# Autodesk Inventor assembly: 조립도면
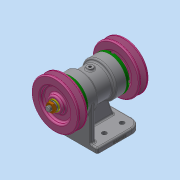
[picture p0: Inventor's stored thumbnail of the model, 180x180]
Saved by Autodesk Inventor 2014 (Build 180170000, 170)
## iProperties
Created: 2020-06
Part Number: 조립도면
Document SubType Name: Weldment
Designer: kh
Weld Material: Welded Aluminum-6061
Author: kh
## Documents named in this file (12)
- C:\Users\kh\Desktop\인벤터시험\조립도면.iam
- C:\Users\kh\Desktop\인벤터시험\본체.ipt
- C:\Users\kh\Desktop\인벤터시험\V-벨트풀리.ipt
- C:\Users\kh\Desktop\인벤터시험\너트 M10.ipt
- C:\Users\kh\Desktop\인벤터시험\베어링 6204.ipt
- C:\Users\kh\Desktop\인벤터시험\볼트 M4.ipt
- C:\Users\kh\Desktop\인벤터시험\스프링 와셔 10.ipt
- C:\Users\kh\Desktop\인벤터시험\오일 실 20 32 5.ipt
- C:\Users\kh\Desktop\인벤터시험\축.ipt
- C:\Users\kh\Desktop\인벤터시험\커버.ipt
- C:\Users\kh\Desktop\인벤터시험\키 5x5x12.ipt
- C:\Users\kh\Desktop\인벤터시험\평면 와셔 10x21.ipt
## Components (2 placed, 1 different names)
1. V-벨트풀리:1 — Angle:2, Mate:24, Mate:26
2. V-벨트풀리:2 — Mate:23, Angle:1, Mate:27, Mate:37
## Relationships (7: Mate 5, Angle 2)
- Mate:23: V-벨트풀리:2
- Angle:1: V-벨트풀리:2
- Angle:2: V-벨트풀리:1
- Mate:24: V-벨트풀리:1
- Mate:26: V-벨트풀리:1
- Mate:27: V-벨트풀리:2
- Mate:37: V-벨트풀리:2
